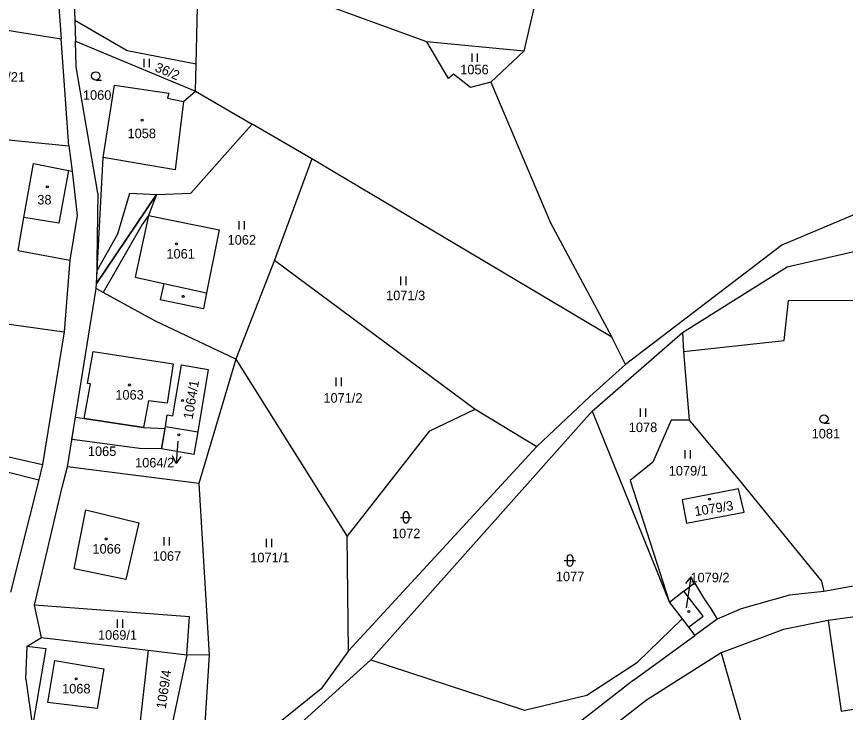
# Model space of a CAD drawing. Extents: x -670359 to -660124, y -978807 to -970072.
# Drawn here: x -670130.3 to -669982.9, y -977711.4 to -977587.7 of the extents above; entities that cross this region are included whole.
import ezdxf

# ---------------------------------------------------------------- set-up
doc = ezdxf.new("R2010")
doc.units = 0
for name, color, linetype in [('Hranice parcel', 7, 'Continuous'), ('Parcelní čísla', 7, 'Continuous'), ('Vnitřní kresba', 7, 'Continuous'), ('Věcná břemena k části', 7, 'Continuous'), ('Značky budov', 7, 'Continuous'), ('Značky kultur', 7, 'Continuous')]:
    doc.layers.add(name, color=color, linetype=linetype)

msp = doc.modelspace()

# ---------------------------------------------------------------- linework, layer by layer
at = {"layer": 'Hranice parcel'}
msp.add_line((-670106.89, -977700.29), (-670100, -977701.17), dxfattribs=at)
for points in [[(-670125.26, -977552.07), (-670122.35, -977591.65)], [(-670033.24, -977564.47), (-670040.09, -977593.86)], [(-670120.58, -977569.54), (-670119.93, -977588.41)], [(-670098.33, -977596.16), (-670097.83, -977573.12)], [(-670057.34, -977592.2), (-670077.72, -977584.8)], [(-670098.33, -977596.16), (-670110.6, -977593.79), (-670119.93, -977588.41)], [(-670119.93, -977588.41), (-670119.81, -977592.06)], [(-670139.34, -977588.92), (-670122.35, -977591.65)], [(-670120.96, -977610.65), (-670122.35, -977591.65)], [(-670119.65, -977596.66), (-670119.81, -977592.06)], [(-670119.81, -977592.06), (-670098.48, -977600.97)], [(-670040.09, -977593.86), (-670057.34, -977592.2)], [(-670053.45, -977598.69), (-670057.34, -977592.2)], [(-670040.09, -977593.86), (-670045.97, -977599.39)], [(-670115.81, -977619.08), (-670119.65, -977596.66)], [(-670098.48, -977600.97), (-670098.33, -977596.16)], [(-670052.56, -977597.95), (-670053.45, -977598.69)], [(-670049.57, -977600.29), (-670052.56, -977597.95)], [(-670114.89, -977612.77), (-670112.88, -977599.91)], [(-670112.88, -977599.91), (-670103.2, -977601.34)], [(-670045.97, -977599.39), (-670049.57, -977600.29)], [(-670045.97, -977599.39), (-670035.35, -977624.36)], [(-670103.2, -977601.34), (-670103.45, -977602.21)], [(-670100.57, -977602.79), (-670098.48, -977600.97)], [(-670098.48, -977600.97), (-670088.41, -977606.81)], [(-670103.45, -977602.21), (-670100.57, -977602.79)], [(-670089.99, -977608.59), (-670088.41, -977606.81)], [(-670077.79, -977612.97), (-670088.41, -977606.81)], [(-670135.99, -977609.18), (-670120.96, -977610.65)], [(-670099.27, -977619.12), (-670089.99, -977608.59)], [(-670120.96, -977610.65), (-670120.4, -977615.18)], [(-670116.08, -977635.17), (-670114.89, -977612.77)], [(-670077.79, -977612.97), (-670084.4, -977630.98)], [(-670024.45, -977644.67), (-670077.79, -977612.97)], [(-670128.95, -977623.4), (-670127.24, -977613.84), (-670121.02, -977615.06)], [(-670121.02, -977615.06), (-670120.4, -977615.18)], [(-670120.4, -977615.18), (-670119.52, -977623.06)], [(-669964.98, -977616.04), (-669994.19, -977628.36)], [(-670115.81, -977619.08), (-670116.08, -977635.17)], [(-670116.08, -977635.17), (-670105.41, -977619.32)], [(-670105.41, -977619.32), (-670099.27, -977619.12)], [(-670130, -977629.28), (-670128.95, -977623.4)], [(-670119.52, -977623.06), (-670120.78, -977631)], [(-670106.8, -977623.06), (-670109.2, -977634)], [(-670106.8, -977623.06), (-670094.25, -977625.63)], [(-670035.35, -977624.36), (-670024.45, -977644.67)], [(-670094.25, -977625.63), (-670096.5, -977636.81)], [(-669993.29, -977632.19), (-669970.04, -977626.86)], [(-669994.19, -977628.36), (-670022.01, -977649.57)], [(-670130, -977629.28), (-670120.78, -977631)], [(-670120.78, -977631), (-670121.83, -977643.75)], [(-670084.4, -977630.98), (-670091.3, -977648.61)], [(-670084.4, -977630.98), (-670048.71, -977657.46)], [(-670011.88, -977643.88), (-669993.29, -977632.19)], [(-670109.2, -977634), (-670104.09, -977635.16)], [(-670116.1, -977636.04), (-670116.08, -977635.17)], [(-670104.09, -977635.16), (-670104.75, -977638.03)], [(-670121.21, -977667.75), (-670116.1, -977636.04)], [(-670105.57, -977641.87), (-670114.88, -977636.72), (-670116.1, -977636.04)], [(-670096.5, -977636.81), (-670097.05, -977639.62)], [(-670097.05, -977639.62), (-670104.75, -977638.03)], [(-670139.74, -977641.23), (-670121.83, -977643.75)], [(-670091.3, -977648.61), (-670105.57, -977641.87)], [(-670121.83, -977643.75), (-670125.68, -977667.32)], [(-670027.91, -977657.85), (-670011.88, -977643.88)], [(-670022.01, -977649.57), (-670024.45, -977644.67)], [(-670011.88, -977643.88), (-670011.67, -977647.24)], [(-670117.66, -977652.9), (-670116.66, -977647.23)], [(-670116.66, -977647.23), (-670102.43, -977649.41)], [(-670011.67, -977647.24), (-670010.71, -977659.41)], [(-670091.3, -977648.61), (-670097.86, -977670.7)], [(-670091.3, -977648.61), (-670071.52, -977680.1)], [(-670102.43, -977649.41), (-670103.52, -977656.44)], [(-670102.48, -977658.66), (-670100.94, -977649.63)], [(-670100.94, -977649.63), (-670096.19, -977650.44)], [(-670096.19, -977650.44), (-670098.07, -977661.52)], [(-670022.01, -977649.57), (-670028.37, -977655.2)], [(-670118.26, -977659.13), (-670117.1, -977652.98)], [(-670117.1, -977652.98), (-670117.66, -977652.9)], [(-670106.8, -977656.02), (-670107.71, -977660.73)], [(-670103.52, -977656.44), (-670106.8, -977656.02)], [(-670028.37, -977655.2), (-670037.79, -977664.1)], [(-670067.28, -977702.04), (-670027.91, -977657.85)], [(-670056.82, -977661.32), (-670048.71, -977657.46)], [(-670048.71, -977657.46), (-670037.79, -977664.1)], [(-670027.91, -977657.85), (-670014.19, -977691.82)], [(-670107.71, -977660.73), (-670118.26, -977659.13)], [(-670103.82, -977660.54), (-670103.47, -977658.49)], [(-670103.47, -977658.49), (-670102.48, -977658.66)], [(-670010.71, -977659.41), (-670013.91, -977659.46)], [(-670010.71, -977659.41), (-670001.99, -977669.86)], [(-670104.5, -977664.53), (-670103.82, -977660.54)], [(-670103.82, -977660.54), (-670098.07, -977661.52)], [(-670013.91, -977659.46), (-670017.17, -977666.88)], [(-670098.07, -977661.52), (-670098.75, -977665.51)], [(-670071.52, -977680.1), (-670056.82, -977661.32)], [(-670143.98, -977663.19), (-670125.68, -977667.32)], [(-670098.75, -977665.51), (-670104.5, -977664.53)], [(-670037.79, -977664.1), (-670071.26, -977700.41)], [(-670125.68, -977667.32), (-670126.34, -977670.04)], [(-670122.19, -977671.34), (-670121.21, -977667.75)], [(-670097.86, -977670.7), (-670121.21, -977667.75)], [(-670017.17, -977666.88), (-670021.19, -977670.13)], [(-670126.34, -977670.04), (-670131.37, -977689.99)], [(-670097.86, -977670.7), (-670096, -977701.2)], [(-670021.19, -977670.13), (-670014.19, -977691.82)], [(-670001.99, -977669.86), (-669987.15, -977688.04)], [(-670127.06, -977692.34), (-670122.19, -977671.34)], [(-670001.92, -977671.66), (-670011.93, -977673.59)], [(-670000.91, -977675.76), (-670001.92, -977671.66)], [(-670011.93, -977673.59), (-670011.14, -977677.72)], [(-670120.05, -977685.88), (-670117.98, -977675.37)], [(-670117.98, -977675.37), (-670108.55, -977677.68)], [(-670011.14, -977677.72), (-670000.91, -977675.76)], [(-670108.55, -977677.68), (-670110.87, -977687.74)], [(-670071.26, -977700.41), (-670071.52, -977680.1)], [(-670110.87, -977687.74), (-670120.05, -977685.88)], [(-669957.62, -977684.64), (-669986.76, -977689.88)], [(-670011.62, -977689.84), (-670009.72, -977688.37)], [(-670009.72, -977688.37), (-670008.14, -977691.01)], [(-669987.15, -977688.04), (-669986.76, -977689.88)], [(-670011.62, -977689.84), (-670014.19, -977691.82)], [(-669986.76, -977689.88), (-669992.85, -977690.56)], [(-670014.19, -977691.82), (-670011.96, -977694.72)], [(-670008.14, -977691.01), (-670006.79, -977693.02)], [(-669992.85, -977690.56), (-670001.43, -977692.98)], [(-670125.86, -977698.04), (-670127.06, -977692.34)], [(-670099.55, -977694.38), (-670127.06, -977692.34)], [(-670006.79, -977693.02), (-670005.69, -977694.79)], [(-670001.43, -977692.98), (-670005.69, -977694.79)], [(-669972.97, -977693.24), (-669985.99, -977695.04)], [(-670100, -977701.17), (-670099.55, -977694.38)], [(-670019.9, -977702.45), (-670011.96, -977694.72)], [(-670011.96, -977694.72), (-670010.79, -977696.24)], [(-670005.69, -977694.79), (-670009.67, -977697.69)], [(-670010.79, -977696.24), (-670009.67, -977697.69)], [(-669985.99, -977695.04), (-669993.94, -977696.63)], [(-669985.99, -977695.04), (-669983.66, -977711.17)], [(-670020.57, -977705.64), (-670009.67, -977697.69)], [(-669993.94, -977696.63), (-670005.01, -977700.79)], [(-670128.4, -977699.61), (-670125.86, -977698.04)], [(-670125.86, -977698.04), (-670106.89, -977700.29)], [(-670128.6, -977705.45), (-670128.4, -977699.61)], [(-670106.89, -977700.29), (-670108.73, -977716.63)], [(-670071.26, -977700.41), (-670076.09, -977707.16)], [(-670124.71, -977709.64), (-670123.45, -977702.13)], [(-670123.45, -977702.13), (-670114.74, -977703.63)], [(-670100, -977701.17), (-670104.16, -977720.69)], [(-670096, -977701.2), (-670100, -977701.17)], [(-670096, -977701.2), (-670097.32, -977721.73)], [(-670097.16, -977729.02), (-670067.28, -977702.04)], [(-670067.28, -977702.04), (-670039.97, -977710.95)], [(-670005.01, -977700.79), (-670018.27, -977709.18)], [(-670005.01, -977700.79), (-669996.13, -977731.83)], [(-670114.74, -977703.63), (-670115.91, -977710.66)], [(-670028.91, -977708.31), (-670019.9, -977702.45)], [(-670128.6, -977705.45), (-670127.44, -977713.87)], [(-670020.57, -977705.64), (-670038.59, -977719.67)], [(-670076.09, -977707.16), (-670097.12, -977724.06)], [(-670039.97, -977710.95), (-670028.91, -977708.31)], [(-670018.27, -977709.18), (-670035.74, -977722.81)], [(-669983.66, -977711.17), (-669966.96, -977708.51)], [(-670115.91, -977710.66), (-670124.71, -977709.64)]]:
    msp.add_lwpolyline(points, dxfattribs=at)
at = {"layer": 'Parcelní čísla'}
for p, q in [((-670101.06, -977665.9), (-670101.92, -977667.14)), ((-670011.25, -977688.45), (-670010.32, -977687.27)), ((-670011.15, -977692.81), (-670010.91, -977691.23))]:
    msp.add_line(p, q, dxfattribs=at)
for points in [[(-670101.57, -977663.15), (-670101.92, -977667.14), (-670102.55, -977665.78)], [(-670010.91, -977691.23), (-670010.32, -977687.27), (-670009.77, -977688.67)]]:
    msp.add_lwpolyline(points, dxfattribs=at)
at = {"layer": 'Vnitřní kresba'}
for points in [[(-670100.57, -977602.79), (-670102.1, -977614.94)], [(-670102.1, -977614.94), (-670114.89, -977612.77)], [(-670121.02, -977615.06), (-670122.74, -977624.45), (-670128.95, -977623.4)], [(-670104.09, -977635.16), (-670096.5, -977636.81)], [(-669993.77, -977645.3), (-669993.01, -977638.18)], [(-669993.01, -977638.18), (-669967.58, -977638.03)], [(-670011.67, -977647.24), (-669993.77, -977645.3)], [(-670138.8, -977666.91), (-670126.34, -977670.04)], [(-670009.61, -977692.44), (-670011.62, -977689.84)], [(-670008.21, -977694.24), (-670009.61, -977692.44)], [(-670010.79, -977696.24), (-670008.21, -977694.24)], [(-670128.4, -977699.61), (-670125.04, -977700.04)], [(-670125.04, -977700.04), (-670127.44, -977713.87)]]:
    msp.add_lwpolyline(points, dxfattribs=at)
at = {"layer": 'Věcná břemena k části'}
for points in [[(-670116.08, -977635.17), (-670105.41, -977619.32), (-670106.8, -977623.06), (-670107.95, -977624.65), (-670114.88, -977636.72), (-670116.1, -977636.04), (-670116.08, -977635.17)], [(-670105.41, -977619.32), (-670116.08, -977635.17)], [(-670115.95, -977632.81), (-670112.28, -977626.3), (-670110.11, -977619.07), (-670105.41, -977619.32)], [(-670116.08, -977635.17), (-670115.95, -977632.81)], [(-670119.78, -977658.9), (-670118.26, -977659.13), (-670107.71, -977660.73), (-670103.89, -977660.93), (-670104.5, -977664.53), (-670108.43, -977664.46), (-670119, -977663.05), (-670120.42, -977662.86), (-670119.78, -977658.9)]]:
    msp.add_lwpolyline(points, dxfattribs=at)
at = {"layer": 'Značky budov'}
for centre in [(-670107.96, -977606.14), (-670124.8, -977617.99), (-670101.83, -977628.08), (-670110.21, -977653.18), (-670100.78, -977655.94), (-670101.44, -977662.05), (-670007.07, -977673.47), (-670114.32, -977680.55), (-670010.74, -977693.45), (-670119.68, -977705.4)]:
    msp.add_circle(centre, 0.175, dxfattribs=at)
at = {"layer": 'Značky kultur'}
for p, q in [((-670049.33, -977594.26), (-670049.33, -977595.76)), ((-670048.33, -977595.76), (-670048.33, -977594.26)), ((-670107.64, -977595.21), (-670107.64, -977596.71)), ((-670106.64, -977596.71), (-670106.64, -977595.21)), ((-670116.19, -977599.01), (-670115.19, -977599.01)), ((-670090.75, -977624.04), (-670090.75, -977625.54)), ((-670089.75, -977625.54), (-670089.75, -977624.04)), ((-670062, -977633.92), (-670062, -977635.42)), ((-670061, -977635.42), (-670061, -977633.92)), ((-670073.52, -977651.88), (-670073.52, -977653.38)), ((-670072.52, -977653.38), (-670072.52, -977651.88)), ((-670019.42, -977657.35), (-670019.42, -977658.85)), ((-670018.42, -977658.85), (-670018.42, -977657.35)), ((-669986.73, -977659.98), (-669985.73, -977659.98)), ((-670011.47, -977664.76), (-670011.47, -977666.26)), ((-670010.47, -977666.26), (-670010.47, -977664.76)), ((-670062.03, -977676.71), (-670060.03, -977676.71)), ((-670061.53, -977676.21), (-670061.53, -977677.21)), ((-670060.53, -977676.21), (-670060.53, -977677.21)), ((-670104.06, -977680.23), (-670104.06, -977681.73)), ((-670103.06, -977681.73), (-670103.06, -977680.23)), ((-670085.91, -977680.51), (-670085.91, -977682.01)), ((-670084.91, -977682.01), (-670084.91, -977680.51)), ((-670032.89, -977684.37), (-670030.89, -977684.37)), ((-670032.39, -977683.87), (-670032.39, -977684.87)), ((-670031.39, -977683.87), (-670031.39, -977684.87)), ((-670112.39, -977694.86), (-670112.39, -977696.36)), ((-670111.39, -977696.36), (-670111.39, -977694.86))]:
    msp.add_line(p, q, dxfattribs=at)
for centre, radius in [((-670116.19, -977598.26), 0.75), ((-670107.96, -977606.14), 0.175), ((-670124.8, -977617.99), 0.175), ((-670101.83, -977628.08), 0.175), ((-670100.65, -977637.43), 0.175), ((-670110.21, -977653.18), 0.175), ((-670100.78, -977655.94), 0.175), ((-669986.73, -977659.23), 0.75), ((-670101.44, -977662.05), 0.175), ((-670007.07, -977673.47), 0.175), ((-670114.32, -977680.55), 0.175), ((-670010.74, -977693.45), 0.175), ((-670119.68, -977705.4), 0.175)]:
    msp.add_circle(centre, radius, dxfattribs=at)
for centre, start, end in [((-670061.03, -977676.21), 0, 180), ((-670061.03, -977677.21), 180, 0), ((-670031.89, -977683.87), 0, 180), ((-670031.89, -977684.87), 180, 0)]:
    msp.add_arc(centre, 0.5, start, end, dxfattribs=at)

# ---------------------------------------------------------------- texts
at = {"layer": 'Parcelní čísla'}
for s, rotation, p in [('36/2', 337.4827, (-670105.81, -977597.37)), ('1064/1', 80.3948, (-670098.97, -977659.34)), ('1079/3', 9.0395, (-670009.6, -977676.49)), ('1069/4', 81.9, (-670103.75, -977710.83))]:
    msp.add_text(s, height=1.7, rotation=rotation, dxfattribs=at).set_placement(p)
for s, height, p in [('27/21', 1.7, (-670134.45, -977599.28)), ('1056', 1.7, (-670051.39, -977597.97)), ('1060', 1.7, (-670118.47, -977602.5)), ('1058', 1.7, (-670110.54, -977609.32)), ('38', 1.7, (-670126.58, -977621.1)), ('1062', 1.7, (-670092.75, -977628.24)), ('1061', 1.7, (-670103.63, -977630.71)), ('1071/3', 1.7, (-670064.57, -977638.11)), ('1063', 1.7, (-670112.71, -977655.78)), ('1071/2', 1.7, (-670075.72, -977656.33)), ('1078', 1.7, (-670021.42, -977661.55)), ('1081', 1.7, (-669988.91, -977662.68)), ('1064/2', 0.1, (-670101.57, -977663.15)), ('1065', 1.7, (-670117.59, -977665.81)), ('1064/2', 1.7, (-670109.2, -977667.84)), ('1079/1', 1.7, (-670014.32, -977669.28)), ('1072', 1.7, (-670063.53, -977680.41)), ('1066', 1.7, (-670116.78, -977683.15)), ('1067', 1.7, (-670106.06, -977684.43)), ('1071/1', 1.7, (-670088.72, -977684.7)), ('1077', 1.7, (-670034.39, -977688.07)), ('1079/2', 1.7, (-670010.46, -977688.26)), ('1079/2', 0.1, (-670011.15, -977692.81)), ('1069/1', 1.7, (-670115.8, -977698.46)), ('1068', 1.7, (-670122.18, -977708))]:
    msp.add_text(s, height=height, dxfattribs=at).set_placement(p)

doc.saveas('drawing.dxf')
